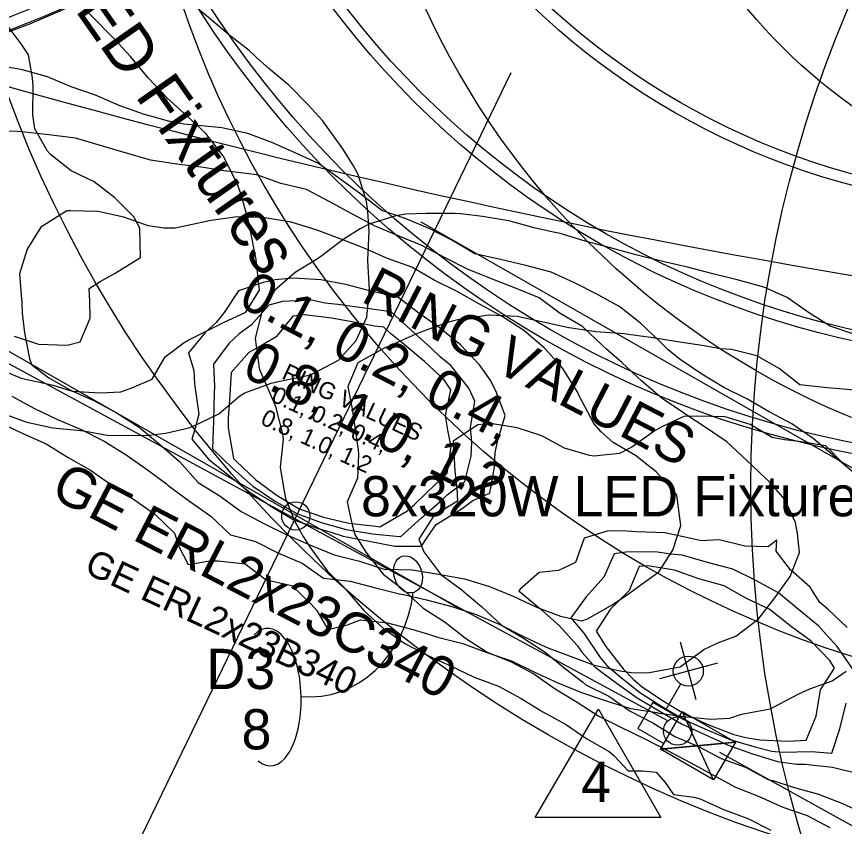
# Model space of a CAD drawing. Extents: x 1638506 to 1658005, y 834807 to 846788.
# Drawn here: x 1640711.8 to 1640958.6, y 842171.5 to 842413 of the extents above; entities that cross this region are included whole.
import ezdxf

# ---------------------------------------------------------------- set-up
doc = ezdxf.new("R2010")
doc.units = 0
for name, color, linetype in [('Default', 7, 'Continuous'), ('Old_Level_1', 7, 'Continuous'), ('Old_Level_2', 7, 'Continuous'), ('Old_Level_4', 7, 'Continuous'), ('Scratch_Level_0', 7, 'Continuous')]:
    doc.layers.add(name, color=color, linetype=linetype)

msp = doc.modelspace()

# ---------------------------------------------------------------- linework, layer by layer
at = {"layer": 'Default'}
for p, q in [((1640656.56, 842338.16), (1640905.62, 842203.16)), ((1640914.34, 842209.21), (1640909.71, 842226.46)), ((1640920.68, 842220.13), (1640903.4, 842215.52)), ((1640912.05, 842217.84), (1640912.05, 842217.84)), ((1640905.34, 842206.22), (1640909.81, 842213.97)), ((1640913.2, 842213.47), (1640913.2, 842213.47)), ((1640919.58, 842185.37), (1640910.22, 842205.74)), ((1640926.06, 842196.59), (1640903.74, 842194.51)), ((1640921.33, 842193.61), (1641098.15, 842095.33))]:
    msp.add_line(p, q, dxfattribs=at)
for points in [[(1640904.76, 842196.26), (1640909.21, 842203.98), (1640901.46, 842208.46), (1640897.01, 842200.74)], [(1640903.81, 842174.17), (1640866.42, 842174.17), (1640885.25, 842206.44)], [(1640919.58, 842185.37), (1640903.74, 842194.51), (1640910.22, 842205.74), (1640926.06, 842196.59)], [(1640914.9, 842195.55), (1640910.22, 842205.74), (1640903.74, 842194.51)], [(1640914.9, 842195.55), (1640926.06, 842196.59), (1640919.58, 842185.37)]]:
    msp.add_lwpolyline(points, close=True, dxfattribs=at)
msp.add_circle((1640912.03, 842217.82), 4.47, dxfattribs=at)
msp.add_ellipse((1640828.45, 842246.66), major_axis=(-1.72, 5.4), ratio=0.730797, dxfattribs=at)
for centre, major_axis, ratio, start_param, end_param in [((1640800.39, 842244.62), (3.78, 34.34), 0.862742, 3.141593, 4.712389), ((1640787.04, 842210.06), (0.49, -20.52), 0.466223, 1.570796, 3.572354), ((1640787.04, 842210.06), (0.49, -20.52), 0.466223, 5.884886, 7.853982)]:
    msp.add_ellipse(centre, major_axis=major_axis, ratio=ratio, start_param=start_param, end_param=end_param, dxfattribs=at)
at = {"layer": 'Old_Level_1'}
for points in [[(1640961.38, 842276.92), (1640955.33, 842282.04), (1640955, 842282.35), (1640949.29, 842287.18), (1640942.88, 842291.54), (1640936.1, 842295.09), (1640929.47, 842298.98), (1640922.62, 842302.4), (1640916.02, 842306.35), (1640909.61, 842310.69), (1640906.01, 842313.63), (1640903.64, 842316), (1640897.81, 842321.59), (1640891.62, 842326.42), (1640884.91, 842330.14), (1640878.08, 842333.58), (1640871.14, 842336.81), (1640863.62, 842338.79), (1640856.02, 842340.59), (1640848.36, 842342.26), (1640841.75, 842346.18), (1640834.94, 842349.68), (1640827.88, 842352.65), (1640820.63, 842355.19), (1640814.42, 842359.99), (1640808.16, 842364.65), (1640801.81, 842369.14), (1640794.88, 842372.38), (1640787.85, 842375.41), (1640780.69, 842378.15), (1640773.01, 842379.79), (1640764.98, 842380.66), (1640761.64, 842380.95), (1640757.07, 842381.82), (1640749.63, 842383.94), (1640742.36, 842386.46), (1640735.34, 842389.51), (1640728.1, 842392.08), (1640721.02, 842394.99), (1640713.56, 842397.1), (1640706.19, 842398.37)], [(1640945.19, 842253.16), (1640944.54, 842258.89), (1640944.01, 842262.15), (1640940.78, 842268.94), (1640936.18, 842274.24), (1640935.23, 842275.14), (1640929.4, 842280.73), (1640923.5, 842286.18), (1640917.08, 842290.52), (1640911.56, 842294.16), (1640910.64, 842294.8), (1640904.2, 842299.1), (1640898.19, 842304.3), (1640892.3, 842309.78), (1640887.61, 842313.77), (1640886.31, 842315.03), (1640880.45, 842320.56), (1640873.8, 842324.41), (1640867.56, 842329.13), (1640860.47, 842332.03), (1640853.32, 842334.79), (1640846.2, 842337.63), (1640839.4, 842341.15), (1640832.63, 842344.74), (1640825.53, 842347.61), (1640818.47, 842350.56), (1640811.72, 842354.19), (1640805, 842357.89), (1640798.23, 842361.46), (1640790.6, 842363.2), (1640783.38, 842365.82), (1640775.37, 842366.76), (1640773.57, 842366.95), (1640767.5, 842367.97), (1640759.52, 842368.96), (1640751.67, 842370.22), (1640744.24, 842372.39), (1640743.16, 842372.69), (1640736.82, 842374.58), (1640729.37, 842376.71), (1640721.4, 842377.72), (1640713.37, 842378.6), (1640712.07, 842378.74), (1640705.05, 842378.86)], [(1640908.58, 842270.23), (1640907.99, 842271.02), (1640902.47, 842277.28), (1640896.26, 842282.07), (1640889.64, 842285.98), (1640886.04, 842289.18), (1640883.85, 842291.66), (1640879.36, 842300.13), (1640879.12, 842300.85), (1640874.62, 842308.06), (1640869.48, 842313.78), (1640869.03, 842314.18), (1640863, 842319.34), (1640856.51, 842323.54), (1640849.81, 842327.28), (1640843.13, 842331.03), (1640836.26, 842334.41), (1640829.64, 842338.31), (1640822.39, 842340.88), (1640815.39, 842343.97), (1640808.21, 842346.67), (1640801.05, 842349.41), (1640793.66, 842351.67), (1640785.83, 842352.98), (1640785.24, 842353.07), (1640777.55, 842353.32), (1640769.14, 842352.13), (1640768.43, 842351.86), (1640759.05, 842349.85), (1640755.75, 842349.94), (1640750.98, 842350.64), (1640743.73, 842353.2), (1640736.07, 842354.87), (1640727.73, 842355.08), (1640726.74, 842355.02), (1640719.04, 842350.17), (1640714.97, 842343.63), (1640712.7, 842336.25), (1640713.36, 842327.5), (1640713.5, 842324.57), (1640714.17, 842318.68), (1640715.6, 842310.98), (1640716.28, 842309.26), (1640721.4, 842305.31), (1640728.06, 842301.5), (1640735.06, 842298.4), (1640741.81, 842294.77), (1640748.3, 842290.59), (1640754.36, 842285.5), (1640760.38, 842280.3), (1640760.48, 842280.2), (1640765.93, 842274.1), (1640772.44, 842269.96), (1640778.75, 842265.39), (1640785.51, 842261.78), (1640792.37, 842258.4), (1640799.38, 842255.32), (1640806.48, 842252.46), (1640814.04, 842250.56), (1640821.4, 842248.24), (1640829.58, 842247.98), (1640829.71, 842247.97), (1640837.56, 842246.7), (1640845.36, 842245.33), (1640852.74, 842243.04), (1640859.86, 842240.2), (1640866.73, 842236.84), (1640873.93, 842234.18), (1640880.25, 842232.8), (1640882, 842233.39), (1640888.82, 842237.24), (1640893.76, 842240.51), (1640896.09, 842242.29), (1640903.22, 842247.41), (1640907.42, 842253.89), (1640909.81, 842261.21), (1640908.58, 842270.23)], [(1640854.26, 842278.68), (1640854.48, 842282.98), (1640855.2, 842286.68), (1640857.42, 842294.08), (1640854.63, 842301.4), (1640852.92, 842304.63), (1640849.8, 842309.15), (1640844.12, 842315.06), (1640838.29, 842319.89), (1640838.02, 842320.09), (1640831.66, 842324.55), (1640825.45, 842329.33), (1640817.8, 842331.02), (1640810.29, 842333.02), (1640809.96, 842333.1), (1640802.52, 842334.46), (1640794.34, 842335.01), (1640788.87, 842334.49), (1640785.3, 842333.73), (1640777.9, 842331.17), (1640773.66, 842324.7), (1640771.28, 842321.78), (1640768.13, 842318.84), (1640763.07, 842312.76), (1640764.6, 842307.44), (1640764.82, 842303.5), (1640766.15, 842294.44), (1640765.01, 842290.23), (1640764, 842287), (1640769.11, 842280.91), (1640775.26, 842275.99), (1640781.38, 842271.02), (1640784.84, 842268.84), (1640787.84, 842266.79), (1640794.49, 842262.94), (1640801.71, 842260.32), (1640805.22, 842259.34), (1640809.11, 842258.09), (1640816.85, 842256.6), (1640824.57, 842255.05), (1640832.53, 842255.05), (1640834.34, 842257.9), (1640836.84, 842261.48), (1640844.63, 842266.28), (1640847.8, 842268.64), (1640852.85, 842270.89), (1640854.26, 842278.68)], [(1640847.26, 842281.94), (1640847.5, 842286.1), (1640847.09, 842290.46), (1640848.37, 842298.31), (1640846.57, 842302.21), (1640841.28, 842308.98), (1640838.04, 842311.57), (1640835.26, 842314.18), (1640829.34, 842319.58), (1640823.42, 842324.98), (1640815.47, 842326.04), (1640807.53, 842327.11), (1640803.75, 842327.55), (1640799.68, 842328.38), (1640791.1, 842328.07), (1640786.95, 842326.95), (1640781.76, 842320.92), (1640778.16, 842318.43), (1640775.13, 842315.58), (1640770.5, 842309.3), (1640770.82, 842302.68), (1640770.7, 842300.76), (1640770.53, 842292.4), (1640770.15, 842284.13), (1640770.45, 842283.78), (1640776.28, 842278.18), (1640782.26, 842272.92), (1640788.68, 842268.58), (1640795.36, 842264.8), (1640802.55, 842262.11), (1640810, 842259.99), (1640817.88, 842258.79), (1640825.91, 842257.92), (1640826.37, 842257.92), (1640832.46, 842263.52), (1640838.76, 842269.02), (1640840.15, 842270.35), (1640845.43, 842274.36), (1640847.26, 842281.94)], [(1640841.37, 842284.69), (1640840.47, 842289.14), (1640839.64, 842293.93), (1640841.21, 842301.64), (1640839.27, 842304.67), (1640833.38, 842310.13), (1640827.29, 842315.17), (1640823.28, 842318.45), (1640821.29, 842320.42), (1640818.51, 842320.67), (1640813.42, 842321.63), (1640805.64, 842323.06), (1640797.67, 842324.06), (1640794.11, 842323.61), (1640789.21, 842317.45), (1640785, 842315), (1640781.02, 842312.83), (1640775.75, 842306.84), (1640775.29, 842298.62), (1640774.89, 842293.31), (1640774.83, 842290.39), (1640776.45, 842281.2), (1640777.3, 842280.37), (1640783.15, 842274.81), (1640789.43, 842270.18), (1640796.03, 842266.24), (1640803.29, 842263.71), (1640810.88, 842261.88), (1640818.9, 842260.98), (1640820.07, 842260.85), (1640828.16, 842265.53), (1640830.36, 842267.45), (1640834.16, 842271.17), (1640840.17, 842276.81), (1640841.37, 842284.69)], [(1640710.4, 842299.83), (1640717.1, 842296.1), (1640724.03, 842292.86), (1640731.09, 842289.89), (1640737.89, 842286.38), (1640744.46, 842282.35), (1640750.79, 842277.84), (1640756.49, 842273.62), (1640757.03, 842273.11), (1640763.31, 842268.47), (1640769.67, 842264.02), (1640775.52, 842258.45), (1640783.04, 842256.49), (1640789.85, 842252.99), (1640796.91, 842250.02), (1640803.25, 842245.52), (1640811.27, 842244.62), (1640818.77, 842242.61), (1640826.36, 842240.78), (1640827.1, 842240.7), (1640833.99, 842239.04), (1640841.52, 842237.09), (1640848.83, 842234.65), (1640855.89, 842231.7), (1640862.7, 842228.19), (1640869.64, 842224.97), (1640876.8, 842222.24), (1640884.01, 842219.59), (1640891.67, 842217.91), (1640895.11, 842217.43), (1640899.84, 842217.33), (1640909.04, 842218.97), (1640909.61, 842219.1), (1640916.66, 842224.26), (1640920.85, 842226.19), (1640926.19, 842228.25), (1640932.46, 842232.99), (1640933.07, 842233.49), (1640937.85, 842239.7), (1640942.39, 842246.02), (1640945.19, 842253.16)], [(1640706.71, 842291.91), (1640713.62, 842288.63), (1640720.62, 842285.54), (1640727.2, 842281.54), (1640733.86, 842277.72), (1640740.2, 842273.21), (1640742.87, 842271.54), (1640746.69, 842269.05), (1640753.04, 842264.56), (1640758.85, 842258.92), (1640760.21, 842255), (1640762.96, 842249.62), (1640769.36, 842250.74), (1640771.91, 842250.72), (1640779.94, 842249.84), (1640786.16, 842245.07), (1640793.81, 842243.37), (1640799.64, 842237.79), (1640801.3, 842235.85), (1640804.56, 842230.22), (1640810.44, 842231.58), (1640814.32, 842233.05), (1640822.37, 842232.23), (1640829.89, 842230.25), (1640834.26, 842228.92), (1640837.26, 842227.95), (1640844.79, 842225.99), (1640852, 842223.35), (1640859.28, 842220.87), (1640866.15, 842217.51), (1640873.11, 842214.31), (1640880.18, 842211.38), (1640887.5, 842208.99), (1640894.84, 842206.63), (1640902.72, 842205.42), (1640902.78, 842205.41), (1640910.64, 842204.3), (1640918.72, 842203.52), (1640924.39, 842203.77), (1640927.84, 842204.98), (1640936.47, 842206.58), (1640937.2, 842206.94), (1640944.96, 842211.06), (1640948.22, 842212.49), (1640954.9, 842214.87), (1640959.13, 842217.78)]]:
    msp.add_lwpolyline(points, dxfattribs=at)
for centre, radius in [((1641016.92, 842574.38), 297), ((1641016.92, 842574.38), 264), ((1640635.3, 842614.58), 219), ((1641016.92, 842574.38), 219), ((1641295.68, 842272.71), 365), ((1640795.03, 842264.09), 4.21)]:
    msp.add_circle(centre, radius, dxfattribs=at)
at = {"layer": 'Old_Level_2'}
for p, q in [((1640394.38, 842493.02), (1640843.22, 842236.75)), ((1640859.16, 842396.17), (1640748.91, 842168.53)), ((1640832.25, 842351.83), (1641022.96, 842242.94))]:
    msp.add_line(p, q, dxfattribs=at)
msp.add_arc((1641349.38, 844661.61), 2358.01, 254.10061, 266.81673, dxfattribs=at)
at = {"layer": 'Old_Level_4'}
for centre, radius in [((1641051.91, 842515.45), 365), ((1640629.86, 842616.81), 219), ((1641051.91, 842515.45), 307), ((1641051.91, 842515.45), 240), ((1641051.91, 842515.45), 158)]:
    msp.add_circle(centre, radius, dxfattribs=at)
at = {"layer": 'Scratch_Level_0'}
for points in [[(1640783.25, 842340.48), (1640783.23, 842340.58), (1640781.3, 842350.12), (1640780.78, 842352.44), (1640778.67, 842360.1), (1640777.65, 842363.02), (1640773.4, 842371.44), (1640773.38, 842371.47), (1640768.24, 842378.09), (1640762.4, 842383.45), (1640756.6, 842388.81), (1640756.58, 842388.83), (1640751.03, 842394.74), (1640745.73, 842401.13), (1640742.31, 842404.85), (1640740.21, 842407.1), (1640734.57, 842412.86), (1640729, 842418.72), (1640725.51, 842422.2), (1640723.5, 842424.73), (1640717.54, 842429.85), (1640710.62, 842433.13)], [(1640817.01, 842331.57), (1640816.59, 842338.41), (1640816.54, 842340.44), (1640816.87, 842348.89), (1640816.51, 842354.86), (1640816.15, 842357.88), (1640813.6, 842365.85), (1640812.25, 842368.52), (1640809, 842373.58), (1640804.01, 842380.57), (1640802.95, 842381.97), (1640798.62, 842386.8), (1640792.97, 842392.52), (1640786.94, 842397.49), (1640783.36, 842400.77), (1640781.1, 842402.86), (1640774.97, 842407.64), (1640768.96, 842412.67), (1640762.95, 842417.7)], [(1640748.55, 842349.89), (1640746.72, 842353.26), (1640741.07, 842358.98), (1640734.91, 842363.71), (1640728.02, 842367.04), (1640721.92, 842371.91), (1640721.02, 842372.81), (1640717.27, 842379.54), (1640716.66, 842383.69), (1640716.76, 842392.26), (1640716.53, 842394.72), (1640715.32, 842401.63), (1640713.17, 842404.85), (1640708.07, 842411.62)], [(1640961.67, 842318.21), (1640954.32, 842320.65), (1640947.85, 842324.79), (1640941.52, 842329.21), (1640934.5, 842332.29), (1640926.97, 842334.39), (1640919.35, 842336.31), (1640911.75, 842338.28), (1640904.87, 842339.9), (1640904.07, 842340.1), (1640896.43, 842341.99), (1640888.86, 842344.01), (1640881.29, 842346.03), (1640873.85, 842348.3), (1640870.85, 842348.95), (1640866.11, 842349.99), (1640858.57, 842352.07), (1640850.64, 842353.4), (1640844.2, 842354.17), (1640842.45, 842354.22), (1640833.86, 842354.29), (1640827.85, 842354.04), (1640824.89, 842353.61), (1640816.9, 842351.11), (1640814.22, 842349.67), (1640809.13, 842346.52), (1640802.41, 842341.39), (1640800.72, 842340.27), (1640794.88, 842336.68), (1640788.67, 842331.29), (1640784.8, 842324.68), (1640782.96, 842317.01), (1640784.1, 842308.28), (1640784.16, 842307.77), (1640787.94, 842299.07), (1640788.94, 842296.67), (1640791.1, 842288.56), (1640791.22, 842286.87), (1640790.4, 842278.67), (1640791.4, 842272.55), (1640791.99, 842269.23), (1640794.77, 842262.43), (1640797.19, 842257.9), (1640799.34, 842254.63), (1640804.36, 842247.7), (1640809.01, 842243.14), (1640810.03, 842242.02), (1640815.4, 842235.78), (1640821.23, 842230.39), (1640827.57, 842226.01), (1640834.36, 842222.48), (1640841.33, 842219.31), (1640848.24, 842216), (1640855.48, 842213.36), (1640862.17, 842209.64), (1640868.71, 842205.63), (1640875.46, 842202.03), (1640881.81, 842197.65), (1640888.42, 842193.79), (1640889.92, 842192.5), (1640894.05, 842188.03), (1640898.47, 842188.05), (1640902.47, 842187.64), (1640905.1, 842184.61), (1640907.63, 842180.98), (1640913.66, 842180.17), (1640915.57, 842179.68), (1640922.54, 842176.49), (1640929.77, 842173.82), (1640936.6, 842170.37)], [(1640711.03, 842317.73), (1640718.37, 842315.28), (1640726.86, 842315.03), (1640730.77, 842316.02), (1640733.73, 842323.1), (1640733.67, 842328.13), (1640733.41, 842331.89), (1640736.71, 842333.99), (1640741.22, 842336.46), (1640748.76, 842341.16), (1640748.55, 842349.89)], [(1640706.03, 842308.12), (1640713.13, 842305.19), (1640720.88, 842303.51), (1640722.34, 842303.16), (1640728.34, 842301.28), (1640736.7, 842300.78), (1640742.88, 842301.11), (1640746.11, 842302.3), (1640752.17, 842304.9), (1640756.12, 842311.48), (1640761.72, 842315.76), (1640762.99, 842316.53), (1640771.46, 842320.75), (1640773.46, 842321.75), (1640780.17, 842324.85), (1640784.23, 842331.36), (1640783.25, 842340.48)], [(1640707.67, 842294.67), (1640714.9, 842292), (1640722.65, 842290.33), (1640730.86, 842289.53), (1640732.35, 842289.34), (1640738.76, 842288.15), (1640747.32, 842288.03), (1640751.23, 842288.16), (1640756.33, 842288.78), (1640763.49, 842290.41), (1640766.54, 842291.84), (1640772.13, 842294.54), (1640778.36, 842299.92), (1640779.81, 842300.8), (1640787.69, 842303.7), (1640790.23, 842304.25), (1640799.52, 842306.17), (1640799.97, 842306.42), (1640807.77, 842310.51), (1640812.99, 842316.42), (1640816.16, 842323.39), (1640817.01, 842331.57)], [(1640961.64, 842301.57), (1640953.39, 842302.28), (1640945.23, 842303.15), (1640939.15, 842308.05), (1640932.49, 842311.83), (1640924.87, 842313.76), (1640921.64, 842313.95), (1640916.79, 842314.8), (1640908.79, 842315.99), (1640900.84, 842317.28), (1640897.79, 842317.71), (1640892.79, 842318.37), (1640884.51, 842319.03), (1640876.48, 842320.17), (1640876.45, 842320.18), (1640868.73, 842321.84), (1640860.99, 842323.53), (1640852.62, 842323.94), (1640852.58, 842323.94), (1640843.25, 842322.57), (1640840.27, 842321.73), (1640832.8, 842319.05), (1640830.59, 842318.14), (1640821.67, 842314.23), (1640821.59, 842314.19), (1640813.56, 842309.74), (1640810.57, 842302.68), (1640811.9, 842295.4), (1640812.22, 842293.2), (1640813.64, 842283.84), (1640813.74, 842282.36), (1640813.46, 842275.31), (1640810.35, 842268.31), (1640811.7, 842261.84), (1640812.59, 842258.52), (1640815.88, 842253.28), (1640821.09, 842246.72), (1640826.08, 842242.89), (1640827.21, 842241.9), (1640833.04, 842236.53), (1640839.52, 842232.41), (1640845.63, 842227.59), (1640852.08, 842223.41), (1640859.22, 842220.55), (1640866.01, 842217.03), (1640872.29, 842212.53), (1640878.86, 842208.58), (1640885.31, 842204.4), (1640892.15, 842200.98), (1640899.04, 842197.63), (1640905.85, 842194.16), (1640912.61, 842190.58), (1640919.31, 842186.87), (1640926.05, 842183.24), (1640933.17, 842180.37), (1640940.18, 842177.27), (1640947.48, 842174.72), (1640954.26, 842171.18)], [(1640958.64, 842279.19), (1640953.05, 842285.02), (1640945.06, 842286.24), (1640940.68, 842286.81), (1640937.07, 842287.45), (1640930.47, 842291.33), (1640923.02, 842293.59), (1640914.54, 842293.87), (1640910.67, 842293.78), (1640904.33, 842290.8), (1640902.18, 842289.57), (1640895.23, 842284.56), (1640891.49, 842282.67), (1640883.82, 842281.87), (1640882.56, 842282.09), (1640875.08, 842284.28), (1640868.39, 842288), (1640860.97, 842290.31), (1640853.05, 842291.65), (1640849.24, 842291.21), (1640841.97, 842286.36), (1640842.46, 842277.49), (1640843.04, 842272.38), (1640843.22, 842268.47), (1640839.99, 842266.52), (1640835.85, 842263.68), (1640831.75, 842257.19), (1640833.19, 842253.42), (1640838.28, 842246.62), (1640844.51, 842242.02), (1640844.8, 842241.79), (1640850.51, 842236.97), (1640856.3, 842231.53), (1640862.91, 842227.65), (1640869.34, 842223.43), (1640875.39, 842218.5), (1640880.48, 842214.64), (1640881.52, 842213.7), (1640888.38, 842210.31), (1640894.68, 842205.84), (1640901.49, 842202.36), (1640908.03, 842198.35), (1640915.07, 842195.31), (1640921.84, 842191.74), (1640929.11, 842189.15), (1640935.83, 842185.49), (1640937.2, 842185.18), (1640943.28, 842183.24), (1640950.8, 842181.12), (1640957.95, 842178.29), (1640964.92, 842175.11)], [(1640959.38, 842230.82), (1640953.57, 842236.23), (1640951.22, 842238.24), (1640948.39, 842242.87), (1640942.46, 842248.04), (1640938.23, 842253.61), (1640938.4, 842256.82), (1640935.87, 842254.83), (1640928.89, 842255.1), (1640921.24, 842256.97), (1640915.82, 842256.62), (1640912.83, 842257.38), (1640905.07, 842259.03), (1640896.6, 842259.32), (1640893.58, 842259.56), (1640888.13, 842259.62), (1640881.03, 842257.45), (1640878.43, 842250.18), (1640873.37, 842247.79), (1640867.58, 842247.2), (1640861.88, 842242.27), (1640861.5, 842241.74), (1640861.57, 842241.66), (1640867.59, 842236.66), (1640873.5, 842231.45), (1640878.96, 842225.36), (1640880.35, 842223.33), (1640884.28, 842219.01), (1640890.48, 842214.34), (1640896.74, 842209.8), (1640903.35, 842205.93), (1640909.97, 842202.08), (1640916.93, 842198.88), (1640923.89, 842195.7), (1640931.21, 842193.18), (1640938.59, 842190.8), (1640944.39, 842190.07), (1640946.85, 842190.1), (1640954.97, 842189.14), (1640962.63, 842187.29)], [(1640961.33, 842217.99), (1640956.44, 842225.17), (1640953.19, 842228.59), (1640950.97, 842231.22), (1640944.9, 842236.14), (1640938.89, 842241.17), (1640932.19, 842244.87), (1640925.32, 842248.22), (1640917.74, 842250.24), (1640910.23, 842252.38), (1640906.8, 842252.69), (1640902.13, 842253.38), (1640893.45, 842253.25), (1640889.95, 842252.82), (1640886.8, 842245.84), (1640881.62, 842239.91), (1640877.03, 842233.67), (1640880.9, 842229.1), (1640885.74, 842221.82), (1640887.78, 842219.47), (1640891.49, 842216.3), (1640897.57, 842211.41), (1640904.08, 842207.34), (1640910.66, 842203.41), (1640917.66, 842200.29), (1640924.73, 842197.3), (1640932.22, 842195.14), (1640936.95, 842193.93), (1640940.05, 842193.61), (1640948.79, 842193.84), (1640954.76, 842193.3), (1640957.22, 842200.64), (1640959.09, 842208.29)], [(1640955.58, 842218.73), (1640954.24, 842220.94), (1640948.64, 842226.75), (1640942.37, 842231.26), (1640936.28, 842236.14), (1640929.4, 842239.49), (1640922.7, 842243.19), (1640915.21, 842245.37), (1640907.91, 842247.91), (1640899.93, 842249.15), (1640897.36, 842248.97), (1640894.43, 842241.88), (1640888.72, 842236.22), (1640884.59, 842229.75), (1640887.48, 842225.16), (1640892.62, 842218.47), (1640895.55, 842215.43), (1640898.41, 842213.02), (1640904.81, 842208.75), (1640911.35, 842204.74), (1640918.39, 842201.7), (1640925.56, 842198.91), (1640929.19, 842197.96), (1640933.35, 842197.31), (1640941.79, 842196.95), (1640947.2, 842197.23), (1640950.12, 842204.33), (1640951.46, 842212.25), (1640955.58, 842218.73)]]:
    msp.add_lwpolyline(points, dxfattribs=at)
for centre, radius in [((1641018.82, 842577.25), 297), ((1641018.82, 842577.25), 264), ((1640634.95, 842614.89), 219), ((1641018.82, 842577.25), 219), ((1640908.84, 842199.91), 4.21)]:
    msp.add_circle(centre, radius, dxfattribs=at)

# ---------------------------------------------------------------- texts
at = {"layer": 'Default'}
for s, p in [('D3', (1640768.38, 842212.46)), ('8', (1640778.84, 842194.46)), ('4', (1640880.07, 842178.78))]:
    msp.add_text(s, height=12, dxfattribs=at).set_placement(p)
at = {"layer": 'Old_Level_1'}
for s, height, rotation, p in [('8x320W LED Fixtures', 14, 305, (1640680.68, 842484.01)), ('RING VALUES', 5, 335, (1640790.55, 842305.19)), ('0.1, 0.2, 0.4,', 5, 335, (1640787.38, 842298.39)), ('0.8, 1.0, 1.2', 5, 335, (1640784.21, 842291.59)), ('GE ERL2x23B340', 8, 335, (1640731.58, 842247.31))]:
    msp.add_text(s, height=height, rotation=rotation, dxfattribs=at).set_placement(p)
at = {"layer": 'Scratch_Level_0'}
for s, p in [('RING VALUES', (1640814.09, 842328.22)), ('0.1, 0.2, 0.4,', (1640777.42, 842326.99)), ('0.8, 1.0, 1.2', (1640778.51, 842306.14)), ('GE ERL2x23C340', (1640721.42, 842269.96))]:
    msp.add_text(s, height=12, rotation=332.5519, dxfattribs=at).set_placement(p)
msp.add_text('8x320W LED Fixtures', height=12, dxfattribs=at).set_placement((1640814.46, 842263.97))

doc.saveas('drawing.dxf')
